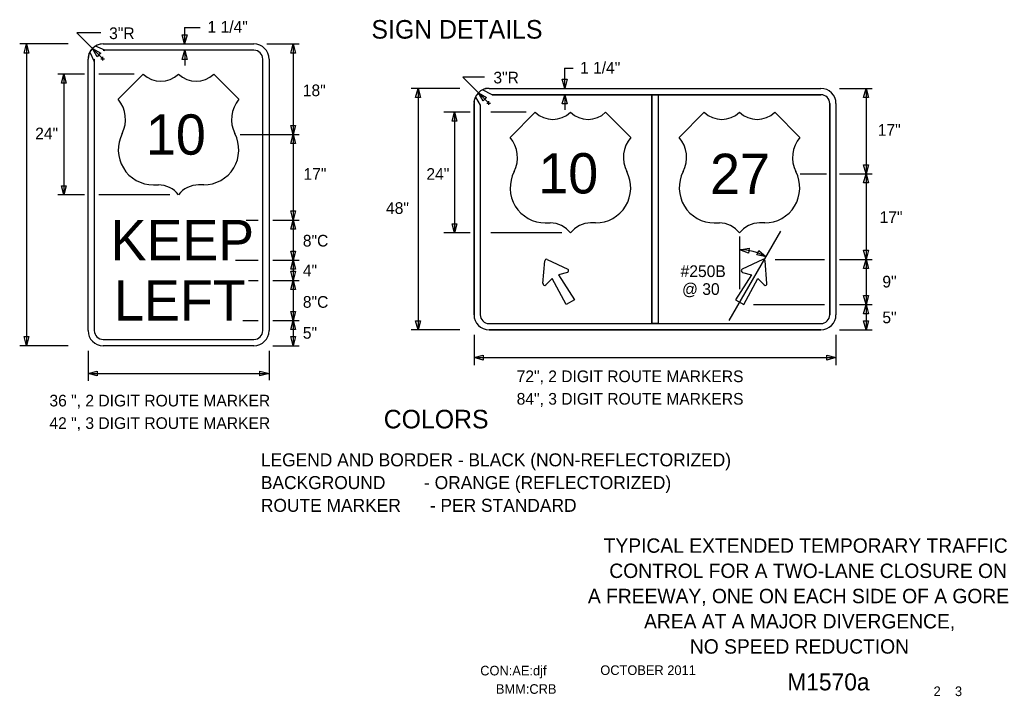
# Model space of a CAD drawing. Extents: x 16563 to 19504, y 6261 to 8279.
# Drawn here: x 17822 to 18461, y 7231 to 7668 of the extents above; entities that cross this region are included whole.
import ezdxf

# ---------------------------------------------------------------- set-up
doc = ezdxf.new("R2010")
doc.units = 0
for name, color, linetype in [('BORDER', 7, 'Continuous'), ('BORDER_SIGNAL_WO', 7, 'Continuous'), ('TRAFFIC_SIGNS_PR', 7, 'Continuous'), ('TYPICAL_EX', 7, 'Continuous'), ('TYPICAL_TEXT_DIMEN_PR', 7, 'Continuous')]:
    doc.layers.add(name, color=color, linetype=linetype)

msp = doc.modelspace()

# ---------------------------------------------------------------- linework, layer by layer
at = {"layer": 'BORDER'}
msp.add_line((18318.25, 7297.5), (18318.25, 7297.5), dxfattribs=at)
at = {"layer": 'TRAFFIC_SIGNS_PR'}
for p, q in [((17877.09, 7648.3), (17870.99, 7651.05)), ((17875.89, 7652.36), (17973.39, 7652.36)), ((17866.14, 7467.11), (17866.14, 7642.61)), ((17868.31, 7648.74), (17867.3, 7647.24)), ((17867.33, 7647.17), (17870.2, 7641.13)), ((17870.2, 7642.61), (17870.2, 7467.11)), ((17973.39, 7648.3), (17875.89, 7648.3)), ((17979.07, 7467.11), (17979.07, 7642.61)), ((17983.14, 7642.61), (17983.14, 7467.11)), ((18125.41, 7623.66), (18339.91, 7623.66)), ((18125.41, 7623.66), (18339.91, 7623.66)), ((18116.58, 7617.93), (18119.72, 7612.88)), ((18127.36, 7619.61), (18121.13, 7622.63)), ((18127.35, 7619.6), (18230.63, 7619.6)), ((18339.91, 7619.6), (18127.35, 7619.6)), ((18230.63, 7619.6), (18230.63, 7471.73)), ((18234.69, 7619.6), (18234.69, 7471.73)), ((18234.69, 7619.6), (18339.91, 7619.6)), ((18115.66, 7613.91), (18115.66, 7477.41)), ((18115.66, 7477.41), (18115.66, 7613.91)), ((18119.72, 7612.86), (18119.72, 7477.41)), ((18119.72, 7612.86), (18119.72, 7477.41)), ((18345.6, 7613.91), (18345.6, 7568.16)), ((18345.6, 7477.41), (18345.6, 7613.91)), ((18349.66, 7613.91), (18349.66, 7477.41)), ((18349.66, 7613.91), (18349.66, 7477.41)), ((18345.6, 7568.16), (18345.6, 7477.41)), ((18160.26, 7497.53), (18161.41, 7512.24)), ((18162.92, 7513.11), (18176.24, 7506.75)), ((18302.39, 7513.11), (18289.08, 7506.75)), ((18305.06, 7497.53), (18303.9, 7512.24)), ((18125.41, 7471.73), (18339.91, 7471.73)), ((18125.41, 7467.66), (18339.91, 7467.66)), ((18339.91, 7467.66), (18125.41, 7467.66)), ((17875.89, 7461.43), (17973.39, 7461.43)), ((17973.39, 7457.36), (17875.89, 7457.36))]:
    msp.add_line(p, q, dxfattribs=at)
for points in [[(18127.35, 7619.6), (18127.33, 7619.61)], [(18119.72, 7612.88), (18119.72, 7612.86)], [(18176.08, 7504.78), (18170.35, 7503.2), (18180.57, 7487.03), (18175.17, 7483.91), (18166.28, 7500.85), (18162.05, 7496.68)], [(18289.24, 7504.78), (18294.96, 7503.2), (18284.75, 7487.03), (18290.14, 7483.91), (18299.04, 7500.85), (18303.26, 7496.68)]]:
    msp.add_lwpolyline(points, dxfattribs=at)
msp.add_lwpolyline([(18230.63, 7619.6), (18234.69, 7619.6), (18234.69, 7471.73), (18230.63, 7471.73)], close=True, dxfattribs=at)
for centre, radius, start, end in [((17875.89, 7642.61), 9.75, 90, 180), ((17875.3, 7644.79), 7.6, 85.58319, 124.53531), ((17973.39, 7642.61), 9.75, 0, 90), ((17873.17, 7643.21), 7.06, 145.86811, 184.82317), ((17864.74, 7641.87), 5.51, 352.24294, 7.75653), ((17876.49, 7652.73), 4.47, 262.2432, 277.7568), ((17973.39, 7642.61), 5.69, 0, 90), ((18125.41, 7613.91), 9.75, 90, 180), ((18125.41, 7613.91), 9.75, 90, 180), ((18124.73, 7617.1), 6.6, 84.11162, 123.06374), ((18339.91, 7613.91), 9.75, 0, 90), ((18339.91, 7613.91), 9.75, 0, 90), ((18121.79, 7614.62), 6.17, 147.60925, 186.56283), ((18126.35, 7626.78), 7.24, 277.81035, 278.05403), ((18339.91, 7613.91), 5.69, 0, 89.99421), ((18339.91, 7613.91), 5.69, 0, 90), ((18162.47, 7512.16), 1.06, 64.48226, 175.51774), ((18302.85, 7512.16), 1.06, 4.48226, 115.51774), ((18175.78, 7505.8), 1.06, 285.9885, 64.48226), ((18289.53, 7505.8), 1.06, 115.51774, 254.0115), ((18161.32, 7497.44), 1.06, 175.51775, 314.01151), ((18304, 7497.44), 1.06, 225.98849, 4.48225), ((18125.41, 7477.41), 9.75, 180, 270), ((18125.41, 7477.41), 9.75, 180, 270), ((18125.41, 7477.41), 5.69, 180, 270), ((18125.41, 7477.41), 5.69, 180, 270), ((18339.91, 7477.41), 9.75, 270, 0), ((18339.91, 7477.41), 5.69, 270, 0), ((18339.91, 7477.41), 9.75, 270, 0), ((18339.91, 7477.41), 5.69, 270, 0), ((17875.89, 7467.11), 9.75, 180, 270), ((17875.89, 7467.11), 5.69, 180, 270), ((17973.39, 7467.11), 5.69, 270, 0), ((17973.39, 7467.11), 9.75, 270, 0)]:
    msp.add_arc(centre, radius, start, end, dxfattribs=at)
at = {"layer": 'TYPICAL_EX'}
for p, q in [((17885.64, 7616.62), (17901.89, 7632.87)), ((17963.64, 7616.62), (17947.39, 7632.87)), ((18139.02, 7592.01), (18155.27, 7608.26)), ((18217.02, 7592.01), (18200.77, 7608.26)), ((18248.3, 7592.01), (18264.55, 7608.26)), ((18326.3, 7592.01), (18310.05, 7608.26)), ((17908.36, 7561.32), (17911.61, 7561.32)), ((17940.91, 7561.32), (17937.66, 7561.32)), ((18161.75, 7536.71), (18165, 7536.71)), ((18194.29, 7536.71), (18191.04, 7536.71)), ((18271.02, 7536.71), (18274.27, 7536.71)), ((18303.57, 7536.71), (18300.32, 7536.71))]:
    msp.add_line(p, q, dxfattribs=at)
for centre, radius, start, end in [((17913.26, 7644.7), 16.42, 226.14041, 313.85958), ((17936.01, 7644.7), 16.42, 226.14042, 313.85959), ((17870.23, 7603.6), 20.16, 333.09768, 40.19361), ((17979.04, 7603.6), 20.16, 139.80639, 206.90233), ((18166.65, 7620.09), 16.42, 226.14041, 313.85958), ((18189.39, 7620.09), 16.42, 226.14042, 313.85959), ((18275.92, 7620.09), 16.42, 226.14041, 313.85958), ((18298.67, 7620.09), 16.42, 226.14042, 313.85959), ((17908.4, 7584.05), 22.73, 152.6698, 269.90132), ((17940.87, 7584.05), 22.73, 270.09868, 27.3302), ((18123.62, 7578.99), 20.16, 333.09768, 40.19361), ((18232.42, 7578.99), 20.16, 139.80639, 206.90233), ((18232.9, 7578.99), 20.16, 333.09768, 40.19361), ((18341.7, 7578.99), 20.16, 139.80639, 206.90233), ((18161.79, 7559.44), 22.73, 152.6698, 269.90132), ((18194.25, 7559.44), 22.73, 270.09868, 27.3302), ((18271.06, 7559.44), 22.73, 152.6698, 269.90132), ((18303.53, 7559.44), 22.73, 270.09868, 27.3302), ((17911.65, 7545.04), 16.28, 37.1038, 90.13853), ((17937.62, 7545.04), 16.28, 89.86147, 142.8962), ((18165.04, 7520.43), 16.28, 37.1038, 90.13853), ((18191, 7520.43), 16.28, 89.86147, 142.8962), ((18274.32, 7520.43), 16.28, 37.1038, 90.13853), ((18300.28, 7520.43), 16.28, 89.86147, 142.8962)]:
    msp.add_arc(centre, radius, start, end, dxfattribs=at)
at = {"layer": 'TYPICAL_TEXT_DIMEN_PR'}
for p, q in [((17928.61, 7663.12), (17928.61, 7652.36)), ((17928.61, 7663.12), (17938.71, 7663.12)), ((17874.51, 7659.65), (17858.85, 7659.65)), ((17858.85, 7659.65), (17869.09, 7649.41)), ((17928.61, 7652.36), (17927.04, 7658.23)), ((17927.04, 7658.23), (17928.61, 7658.23)), ((17928.61, 7658.23), (17930.18, 7658.23)), ((17930.18, 7658.23), (17928.61, 7652.36)), ((17853.31, 7652.36), (17822.01, 7652.36)), ((17824.78, 7646.5), (17826.35, 7652.36)), ((17826.35, 7652.36), (17826.35, 7457.36)), ((17826.35, 7652.36), (17827.92, 7646.5)), ((17869.09, 7649.41), (17875.65, 7642.85)), ((17872.12, 7644.15), (17869.09, 7649.41)), ((17869.09, 7649.41), (17874.34, 7646.38)), ((17981.68, 7652.36), (18002.64, 7652.36)), ((17997.17, 7646.5), (17998.74, 7652.36)), ((17998.74, 7652.36), (17998.74, 7593.86)), ((17998.74, 7652.36), (18000.31, 7646.5)), ((17826.35, 7646.5), (17824.78, 7646.5)), ((17827.92, 7646.5), (17826.35, 7646.5)), ((17873.23, 7645.27), (17872.12, 7644.15)), ((17874.34, 7646.38), (17873.23, 7645.27)), ((17874.44, 7642.85), (17876.85, 7642.85)), ((17875.65, 7641.65), (17875.65, 7644.06)), ((17927.09, 7642.44), (17928.66, 7648.3)), ((17928.66, 7648.3), (17928.66, 7638.55)), ((17928.66, 7648.3), (17930.23, 7642.44)), ((17998.74, 7646.5), (17997.17, 7646.5)), ((18000.31, 7646.5), (17998.74, 7646.5)), ((17928.66, 7642.44), (17927.09, 7642.44)), ((17930.23, 7642.44), (17928.66, 7642.44)), ((18174.26, 7636.82), (18174.26, 7623.66)), ((18174.26, 7636.82), (18179.79, 7636.82)), ((17863.76, 7632.86), (17846.64, 7632.86)), ((17848.96, 7627), (17850.53, 7632.86)), ((17850.53, 7632.86), (17850.53, 7554.86)), ((17850.53, 7632.86), (17852.1, 7627)), ((17896, 7632.86), (17873.13, 7632.86)), ((18122.55, 7630.95), (18108.37, 7630.95)), ((18108.37, 7630.95), (18118.52, 7620.8)), ((17850.53, 7627), (17848.96, 7627)), ((17852.1, 7627), (17850.53, 7627)), ((18106.42, 7623.66), (18075.13, 7623.66)), ((18077.9, 7617.8), (18079.47, 7623.66)), ((18079.47, 7623.66), (18079.47, 7467.66)), ((18079.47, 7623.66), (18081.04, 7617.8)), ((18174.27, 7623.66), (18172.69, 7629.53)), ((18172.69, 7629.53), (18174.27, 7629.53)), ((18174.27, 7629.53), (18175.84, 7629.53)), ((18175.84, 7629.53), (18174.27, 7623.66)), ((18352.03, 7623.66), (18372.99, 7623.66)), ((18367.52, 7617.8), (18369.09, 7623.66)), ((18369.09, 7623.66), (18369.09, 7568.41)), ((18369.09, 7623.66), (18370.67, 7617.8)), ((18079.47, 7617.8), (18077.9, 7617.8)), ((18081.04, 7617.8), (18079.47, 7617.8)), ((18118.52, 7620.8), (18125.17, 7614.16)), ((18121.56, 7615.55), (18118.52, 7620.8)), ((18118.52, 7620.8), (18123.78, 7617.77)), ((18123.78, 7617.77), (18122.67, 7616.66)), ((18172.74, 7613.74), (18174.31, 7619.6)), ((18172.74, 7613.74), (18174.31, 7619.6)), ((18174.31, 7619.6), (18174.31, 7609.85)), ((18174.31, 7619.6), (18175.89, 7613.74)), ((18174.31, 7619.6), (18175.89, 7613.74)), ((18369.09, 7617.8), (18367.52, 7617.8)), ((18370.67, 7617.8), (18369.09, 7617.8)), ((18122.67, 7616.66), (18121.56, 7615.55)), ((18123.96, 7614.16), (18126.38, 7614.16)), ((18125.17, 7612.95), (18125.17, 7615.36)), ((18174.31, 7613.74), (18172.74, 7613.74)), ((18174.31, 7613.74), (18172.74, 7613.74)), ((18175.89, 7613.74), (18174.31, 7613.74)), ((18175.89, 7613.74), (18174.31, 7613.74)), ((18113.28, 7608.25), (18096.16, 7608.25)), ((18101.46, 7602.39), (18103.03, 7608.25)), ((18103.03, 7608.25), (18103.03, 7530.25)), ((18103.03, 7608.25), (18104.6, 7602.39)), ((18149.39, 7608.25), (18126.51, 7608.25)), ((17998.74, 7593.86), (17997.17, 7599.73)), ((17997.17, 7599.73), (17998.74, 7599.73)), ((17998.74, 7599.73), (18000.31, 7599.73)), ((18000.31, 7599.73), (17998.74, 7593.86)), ((18103.03, 7602.39), (18101.46, 7602.39)), ((18104.6, 7602.39), (18103.03, 7602.39)), ((17964.53, 7593.86), (18002.64, 7593.86)), ((17997.17, 7588), (17998.74, 7593.86)), ((17998.74, 7593.86), (17998.74, 7538.61)), ((17998.74, 7593.86), (18000.31, 7588)), ((17998.74, 7588), (17997.17, 7588)), ((18000.31, 7588), (17998.74, 7588)), ((18369.09, 7568.41), (18367.52, 7574.28)), ((18367.52, 7574.28), (18369.09, 7574.28)), ((18369.09, 7574.28), (18370.67, 7574.28)), ((18370.67, 7574.28), (18369.09, 7568.41)), ((18326.47, 7568.41), (18343.62, 7568.41)), ((18352.03, 7568.41), (18372.99, 7568.41)), ((18367.52, 7562.55), (18369.09, 7568.41)), ((18369.09, 7568.41), (18369.09, 7513.16)), ((18369.09, 7568.41), (18370.67, 7562.55)), ((17850.53, 7554.86), (17848.96, 7560.73)), ((17848.96, 7560.73), (17850.53, 7560.73)), ((17850.53, 7560.73), (17852.1, 7560.73)), ((17852.1, 7560.73), (17850.53, 7554.86)), ((18369.09, 7562.55), (18367.52, 7562.55)), ((18370.67, 7562.55), (18369.09, 7562.55)), ((17863.76, 7554.86), (17846.64, 7554.86)), ((17919.13, 7554.86), (17873.13, 7554.86)), ((17998.74, 7538.61), (17997.17, 7544.48)), ((17997.17, 7544.48), (17998.74, 7544.48)), ((17998.74, 7544.48), (18000.31, 7544.48)), ((18000.31, 7544.48), (17998.74, 7538.61)), ((17968.47, 7538.61), (17976.15, 7538.61)), ((17985.51, 7538.61), (18002.64, 7538.61)), ((17997.17, 7532.75), (17998.74, 7538.61)), ((17998.74, 7538.61), (17998.74, 7512.61)), ((17998.74, 7538.61), (18000.31, 7532.75)), ((18103.03, 7530.25), (18101.46, 7536.11)), ((18101.46, 7536.11), (18103.03, 7536.11)), ((18103.03, 7536.11), (18104.6, 7536.11)), ((18104.6, 7536.11), (18103.03, 7530.25)), ((17998.74, 7532.75), (17997.17, 7532.75)), ((18000.31, 7532.75), (17998.74, 7532.75)), ((18113.28, 7530.25), (18096.16, 7530.25)), ((18172.51, 7530.25), (18126.51, 7530.25)), ((18280.69, 7473.76), (18313.93, 7531.35)), ((18287.45, 7493.92), (18287.45, 7527.91)), ((17998.74, 7512.61), (17997.17, 7518.48)), ((17997.17, 7518.48), (17998.74, 7518.48)), ((17998.74, 7518.48), (18000.31, 7518.48)), ((18000.31, 7518.48), (17998.74, 7512.61)), ((18287.48, 7519.36), (18293.47, 7520.32)), ((18293.15, 7517.19), (18287.48, 7519.36)), ((18293.31, 7518.76), (18293.15, 7517.19)), ((18293.47, 7520.32), (18293.31, 7518.76)), ((18298.46, 7516.03), (18299.15, 7517.45)), ((18304.43, 7514.9), (18298.46, 7516.03)), ((18299.15, 7517.45), (18299.83, 7518.86)), ((18299.83, 7518.86), (18304.43, 7514.9)), ((18369.09, 7513.16), (18367.52, 7519.03)), ((18367.52, 7519.03), (18369.09, 7519.03)), ((18369.09, 7519.03), (18370.67, 7519.03)), ((18370.67, 7519.03), (18369.09, 7513.16)), ((17961.45, 7512.61), (17976.15, 7512.61)), ((17985.51, 7512.61), (18002.64, 7512.61)), ((17997.17, 7506.75), (17998.74, 7512.61)), ((17998.74, 7512.61), (17998.74, 7499.61)), ((17998.74, 7512.61), (18000.31, 7506.75)), ((18310.4, 7513.16), (18342.27, 7513.16)), ((18352.03, 7513.16), (18372.99, 7513.16)), ((18367.52, 7507.3), (18369.09, 7513.16)), ((18369.09, 7513.16), (18369.09, 7483.91)), ((18369.09, 7513.16), (18370.67, 7507.3)), ((17998.74, 7506.75), (17997.17, 7506.75)), ((17998.74, 7499.61), (17997.17, 7505.48)), ((17997.17, 7505.48), (17998.74, 7505.48)), ((18000.31, 7506.75), (17998.74, 7506.75)), ((17998.74, 7505.48), (18000.31, 7505.48)), ((18000.31, 7505.48), (17998.74, 7499.61)), ((18369.09, 7507.3), (18367.52, 7507.3)), ((18370.67, 7507.3), (18369.09, 7507.3)), ((17969.8, 7499.61), (17976.15, 7499.61)), ((17985.51, 7499.61), (18002.64, 7499.61)), ((17997.17, 7493.75), (17998.74, 7499.61)), ((17998.74, 7499.61), (17998.74, 7473.61)), ((17998.74, 7499.61), (18000.31, 7493.75)), ((17998.74, 7493.75), (17997.17, 7493.75)), ((18000.31, 7493.75), (17998.74, 7493.75)), ((18369.09, 7483.91), (18367.52, 7489.78)), ((18367.52, 7489.78), (18369.09, 7489.78)), ((18369.09, 7489.78), (18370.67, 7489.78)), ((18370.67, 7489.78), (18369.09, 7483.91)), ((18296.26, 7483.91), (18342.27, 7483.91)), ((18352.03, 7483.91), (18372.99, 7483.91)), ((18367.52, 7478.05), (18369.09, 7483.91)), ((18369.09, 7483.91), (18369.09, 7467.66)), ((18369.09, 7483.91), (18370.67, 7478.05)), ((17998.74, 7473.61), (17997.17, 7479.48)), ((17997.17, 7479.48), (17998.74, 7479.48)), ((17998.74, 7479.48), (18000.31, 7479.48)), ((18000.31, 7479.48), (17998.74, 7473.61)), ((18369.09, 7478.05), (18367.52, 7478.05)), ((18370.67, 7478.05), (18369.09, 7478.05)), ((17966.3, 7473.61), (17976.15, 7473.61)), ((17985.51, 7473.61), (18002.64, 7473.61)), ((17997.17, 7467.75), (17998.74, 7473.61)), ((17998.74, 7473.61), (17998.74, 7457.36)), ((17998.74, 7473.61), (18000.31, 7467.75)), ((18079.47, 7467.66), (18077.9, 7473.53)), ((18077.9, 7473.53), (18079.47, 7473.53)), ((18079.47, 7473.53), (18081.04, 7473.53)), ((18081.04, 7473.53), (18079.47, 7467.66)), ((18369.09, 7467.66), (18367.52, 7473.53)), ((18367.52, 7473.53), (18369.09, 7473.53)), ((18369.09, 7473.53), (18370.67, 7473.53)), ((18370.67, 7473.53), (18369.09, 7467.66)), ((17998.74, 7467.75), (17997.17, 7467.75)), ((18000.31, 7467.75), (17998.74, 7467.75)), ((18106.42, 7467.66), (18075.13, 7467.66)), ((18115.66, 7464.32), (18115.66, 7444.76)), ((18349.66, 7464.32), (18349.66, 7444.76)), ((18352.03, 7467.66), (18369.16, 7467.66)), ((18352.03, 7467.66), (18372.99, 7467.66)), ((18352.03, 7467.66), (18369.16, 7467.66)), ((17853.31, 7457.36), (17822.01, 7457.36)), ((17826.35, 7457.36), (17824.78, 7463.23)), ((17824.78, 7463.23), (17826.35, 7463.23)), ((17826.35, 7463.23), (17827.92, 7463.23)), ((17827.92, 7463.23), (17826.35, 7457.36)), ((17985.51, 7457.36), (18002.64, 7457.36)), ((17998.74, 7457.36), (17997.17, 7463.23)), ((17997.17, 7463.23), (17998.74, 7463.23)), ((17998.74, 7463.23), (18000.31, 7463.23)), ((18000.31, 7463.23), (17998.74, 7457.36)), ((17866.14, 7454.02), (17866.14, 7434.67)), ((17983.14, 7454.02), (17983.14, 7435.12)), ((18115.66, 7449.69), (18121.52, 7451.26)), ((18121.52, 7451.26), (18121.52, 7449.69)), ((18343.8, 7449.69), (18343.8, 7451.26)), ((18343.8, 7451.26), (18349.66, 7449.69)), ((18115.66, 7449.69), (18349.66, 7449.69)), ((18121.52, 7448.12), (18115.66, 7449.69)), ((18121.52, 7449.69), (18121.52, 7448.12)), ((18349.66, 7449.69), (18343.8, 7448.12)), ((18343.8, 7448.12), (18343.8, 7449.69)), ((17866.14, 7439.39), (17872, 7440.96)), ((17866.14, 7439.39), (17983.14, 7439.39)), ((17872, 7437.82), (17866.14, 7439.39)), ((17872, 7440.96), (17872, 7439.39)), ((17872, 7439.39), (17872, 7437.82)), ((17977.28, 7439.39), (17977.28, 7440.96)), ((17977.28, 7440.96), (17983.14, 7439.39)), ((17983.14, 7439.39), (17977.28, 7437.82)), ((17977.28, 7437.82), (17977.28, 7439.39))]:
    msp.add_line(p, q, dxfattribs=at)
msp.add_arc((18287.64, 7484.92), 34.39, 60.74521, 90.32117, dxfattribs=at)

# ---------------------------------------------------------------- texts
at = {"layer": 'BORDER'}
for s, p in [('TYPICAL EXTENDED TEMPORARY TRAFFIC', (18199.5, 7323.57)), ('CONTROL FOR A TWO-LANE CLOSURE ON', (18203.14, 7307.27)), ('A FREEWAY, ONE ON EACH SIDE OF A GORE', (18189.3, 7290.97)), ('AREA AT A MAJOR DIVERGENCE,', (18225.61, 7274.67)), ('NO SPEED REDUCTION', (18255.23, 7258.37))]:
    msp.add_text(s, height=9.3, dxfattribs=at).set_placement(p)
at = {"layer": 'BORDER_SIGNAL_WO'}
for s, height, p in [('CON:AE:djf  ', 6.2, (18119.69, 7244.31)), ('    OCTOBER 2011    ', 6.2, (18188.08, 7244.59)), ('    M1570a   ', 11, (18301.86, 7234.63)), ('BMM:CRB   ', 6.2, (18129.81, 7232.42)), (' 2    3 ', 6.2, (18410.45, 7230.95))]:
    msp.add_text(s, height=height, dxfattribs=at).set_placement(p)
at = {"layer": 'TRAFFIC_SIGNS_PR'}
for s, p in [('10', (17903.61, 7580.86)), ('10', (18157.26, 7555.79)), ('27', (18268.26, 7555.44)), ('KEEP', (17880.74, 7512.61)), ('LEFT', (17882.97, 7473.61))]:
    msp.add_text(s, height=26, dxfattribs=at).set_placement(p)
at = {"layer": 'TYPICAL_TEXT_DIMEN_PR'}
for s, height, p in [('3"R', 7.55, (17879.78, 7655.52)), ('1 1/4"', 7.55, (17943.41, 7659.62)), ('SIGN DETAILS', 12, (18049.36, 7655.83)), ('1 1/4"', 7.55, (18184.19, 7633.24)), ('3"R', 7.55, (18128.19, 7626.87)), ('18"', 7.55, (18004.98, 7618.63)), ('24"', 7.55, (17831.98, 7590.75)), ('17"', 7.55, (18376.67, 7593.02)), ('24"', 7.55, (18084.88, 7564.58)), ('17"', 7.55, (18005.44, 7564.59)), ('48"', 7.55, (18058.77, 7542.56)), ('17"', 7.55, (18377.87, 7536.67)), ('8"C', 7.55, (18005.01, 7521.47)), ('4" ', 7.55, (18005.01, 7502.21)), ('#250B', 7.55, (18249.22, 7501.76)), ('9"', 7.55, (18379.65, 7495.01)), ('@ 30', 7.55, (18250.16, 7490.21)), ('8"C', 7.55, (18005.01, 7481.88)), ('5"', 7.55, (18379.65, 7471.91)), ('5" ', 7.55, (18005.01, 7461.91)), ('72", 2 DIGIT ROUTE MARKERS', 7.55, (18143.24, 7433.83)), ('36 ", 2 DIGIT ROUTE MARKER', 7.55, (17841.18, 7418.13)), ('84", 3 DIGIT ROUTE MARKERS', 7.55, (18143.24, 7419.28)), ('COLORS', 12, (18057.3, 7403.95)), ('42 ", 3 DIGIT ROUTE MARKER', 7.55, (17841.18, 7403.58)), ('LEGEND AND BORDER - BLACK (NON-REFLECTORIZED)', 8.4, (17977.88, 7379.42)), ('BACKGROUND        - ORANGE (REFLECTORIZED)', 8.4, (17977.88, 7364.72)), ('ROUTE MARKER      - PER STANDARD', 8.4, (17977.88, 7350.02))]:
    msp.add_text(s, height=height, dxfattribs=at).set_placement(p)

doc.saveas('drawing.dxf')
